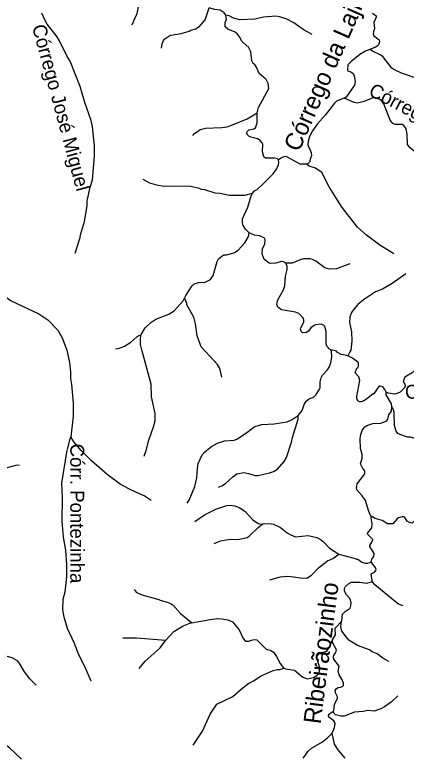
# Model space of a CAD drawing. Extents: x 393 to 446.6, y 8175.5 to 8231.
# Drawn here: x 426.13 to 430.63, y 8175.61 to 8184.16 of the extents above; entities that cross this region are included whole.
import ezdxf
from ezdxf.enums import TextEntityAlignment as Align

# ---------------------------------------------------------------- set-up
doc = ezdxf.new("R2010")
doc.units = 0
doc.header["$LTSCALE"] = 0.064
doc.linetypes.add('LONG_DASHED', pattern=[7.5, 6, -1.5])
doc.layers.add('61', color=7, linetype='Continuous')
doc.layers.add('7', color=7, linetype='Continuous', lineweight=25)
doc.layers.add('9', color=7, linetype='LONG_DASHED', lineweight=25)

msp = doc.modelspace()

# ---------------------------------------------------------------- linework, layer by layer
at = {"layer": '7'}
for points in [[(427.4826, 8184.0466), (427.5145, 8184.1177), (427.5416, 8184.178), (427.5642, 8184.2943), (427.5642, 8184.3976), (427.5093, 8184.5656), (427.506, 8184.6176)], [(427.8211, 8183.7769), (427.829, 8183.8292), (427.8452, 8183.8648), (427.8597, 8183.8857), (427.9033, 8183.9148), (427.9198, 8183.923), (427.926, 8183.9261), (428.0455, 8183.9455), (428.1391, 8183.9745), (428.1585, 8183.9858), (428.215, 8183.9987), (428.2473, 8184.0246), (428.2554, 8184.0246), (428.3216, 8184.1021), (428.3699, 8184.2432)], [(428.5594, 8184.1583), (428.542, 8184.1851), (428.496, 8184.2135), (428.4298, 8184.2232), (428.3699, 8184.2432)], [(426.8263, 8181.4239), (426.886, 8181.6024), (426.8892, 8181.6331), (426.9344, 8181.7849), (426.9635, 8181.9658), (426.9667, 8182.0239), (426.999, 8182.1789), (427.0265, 8182.2661), (427.0507, 8182.5374), (427.0491, 8182.6537), (427.0249, 8182.8733), (427.0103, 8182.9475), (426.9393, 8183.1542), (426.886, 8183.3383), (426.7681, 8183.629), (426.7358, 8183.6823), (426.6438, 8183.868), (426.6099, 8183.9229), (426.5065, 8184.0521), (426.4774, 8184.1037), (426.4451, 8184.1813)], [(428.9217, 8183.0345), (428.9352, 8183.0961), (429.0531, 8183.3157), (429.0482, 8183.3722), (429.0224, 8183.4191), (428.9432, 8183.4853), (428.9142, 8183.5579), (428.8884, 8183.5935), (428.8738, 8183.6031), (428.8651, 8183.6228), (428.8609, 8183.6322), (428.848, 8183.7356), (428.8173, 8183.7985), (428.8076, 8183.8017), (428.7446, 8183.8599), (428.7188, 8183.91), (428.6946, 8183.939), (428.6687, 8183.96), (428.5848, 8183.9972), (428.5525, 8184.0246), (428.5525, 8184.0682), (428.5686, 8184.1102), (428.5594, 8184.1583)], [(429.5529, 8183.9345), (429.4503, 8183.9907), (429.3437, 8184.0682), (429.2533, 8184.1134), (429.1758, 8184.1392), (429.1371, 8184.1473), (428.9917, 8184.1344), (428.8948, 8184.1118), (428.7204, 8184.1021), (428.6494, 8184.1215), (428.5977, 8184.1489), (428.5594, 8184.1583)], [(428.18, 8182.7749), (428.2021, 8182.8006), (428.2441, 8182.8297), (428.2667, 8182.8426), (428.3264, 8182.8587), (428.5137, 8182.8668), (428.5751, 8182.8748), (428.6171, 8182.8878), (428.8044, 8182.9653), (428.9217, 8183.0345)], [(429.1657, 8182.4939), (429.154, 8182.5067), (429.1209, 8182.5131), (429.0176, 8182.5131), (428.9965, 8182.5293), (428.9804, 8182.5858), (428.9869, 8182.6762), (428.9788, 8182.6892), (428.9562, 8182.7182), (428.9239, 8182.7344), (428.8464, 8182.7538), (428.8238, 8182.7667), (428.8124, 8182.7763), (428.7995, 8182.8054), (428.8044, 8182.8184), (428.8254, 8182.8377), (428.8819, 8182.849), (428.9013, 8182.8635), (428.919, 8182.9217), (428.9217, 8183.0345)], [(428.8689, 8182.1099), (428.891, 8182.1367), (428.919, 8182.1547), (428.9917, 8182.2209), (429.1031, 8182.3323), (429.1435, 8182.3856), (429.1677, 8182.4373), (429.1709, 8182.4631), (429.1657, 8182.4939)], [(427.6061, 8182.2736), (427.6837, 8182.2305), (427.7613, 8182.2063), (427.8517, 8182.1934), (427.9712, 8182.1967), (428.1585, 8182.1902), (428.2537, 8182.1692), (428.2748, 8182.1579), (428.3135, 8182.153), (428.433, 8182.1159), (428.4944, 8182.1111), (428.6009, 8182.0884), (428.7786, 8182.09), (428.8689, 8182.1099)], [(428.8273, 8181.6561), (428.7866, 8181.6961), (428.7592, 8181.7397), (428.7511, 8181.772), (428.7511, 8181.8156), (428.8125, 8181.9496), (428.8526, 8182.0797), (428.8689, 8182.1099)], [(428.0861, 8180.905), (428.102, 8180.9366), (428.1681, 8181.0437), (428.1972, 8181.0679), (428.2457, 8181.0856), (428.3216, 8181.0905), (428.3846, 8181.1212), (428.4152, 8181.1648), (428.4588, 8181.3263), (428.4766, 8181.3554), (428.5137, 8181.3892), (428.5364, 8181.4021), (428.567, 8181.4021), (428.6413, 8181.4215), (428.6607, 8181.428), (428.7011, 8181.4554), (428.7801, 8181.541), (428.8205, 8181.6137), (428.8273, 8181.6561)], [(429.2516, 8181.3073), (429.2242, 8181.3214), (429.1952, 8181.3247), (429.1338, 8181.3085), (429.0692, 8181.3037), (429.0595, 8181.3053), (429.0078, 8181.3473), (428.9965, 8181.3618), (428.9772, 8181.4135), (428.9836, 8181.4716), (429.0095, 8181.5298), (429.0127, 8181.5766), (429.003, 8181.5976), (428.9465, 8181.6218), (428.8884, 8181.6299), (428.8273, 8181.6561)], [(429.7687, 8180.3121), (429.7396, 8180.3272), (429.7361, 8180.3396), (429.7216, 8180.3542), (429.7151, 8180.38), (429.7135, 8180.5221), (429.699, 8180.5786), (429.6861, 8180.5899), (429.657, 8180.6061), (429.5924, 8180.5996), (429.5775, 8180.5899), (429.5375, 8180.5641), (429.5149, 8180.5285), (429.489, 8180.5092), (429.4439, 8180.506), (429.4261, 8180.5205), (429.4196, 8180.548), (429.4228, 8180.5657), (429.4584, 8180.6287), (429.4584, 8180.6545), (429.4519, 8180.6707), (429.4422, 8180.6884), (429.4003, 8180.7272), (429.3599, 8180.745), (429.2016, 8180.7724), (429.1596, 8180.8031), (429.1483, 8180.8305), (429.1564, 8180.8774), (429.2242, 8181.0001), (429.2388, 8181.0453), (429.2484, 8181.1584), (429.2646, 8181.2359), (429.2662, 8181.273), (429.2516, 8181.3073)], [(429.9862, 8181.2983), (429.8314, 8181.2439), (429.7539, 8181.2391), (429.699, 8181.252), (429.594, 8181.3295), (429.5569, 8181.3505), (429.5311, 8181.3569), (429.4536, 8181.3553), (429.4148, 8181.3472), (429.3244, 8181.3085), (429.2516, 8181.3073)], [(430.6311, 8181.1829), (430.4741, 8181.0744), (430.3611, 8181.0082), (430.2836, 8180.9758), (430.1447, 8180.887), (430.0768, 8180.8321), (430.0365, 8180.7821), (430.0074, 8180.7385), (429.988, 8180.6868), (429.9815, 8180.6255), (430.0042, 8180.5189), (430.0106, 8180.4091), (429.9977, 8180.3057), (429.9881, 8180.2889), (429.9622, 8180.2431)], [(427.5833, 8180.4796), (427.6336, 8180.5641), (427.6967, 8180.6238), (427.7548, 8180.6626), (427.9066, 8180.7223), (427.9679, 8180.7611), (428.0713, 8180.8757), (428.0861, 8180.905)], [(428.5141, 8179.9975), (428.5008, 8180.0668), (428.4879, 8180.1055), (428.4653, 8180.1443), (428.278, 8180.3445), (428.2295, 8180.4705), (428.2117, 8180.6093), (428.1908, 8180.6868), (428.11, 8180.8289), (428.11, 8180.8435), (428.0869, 8180.9028), (428.0861, 8180.905)], [(427.2894, 8180.3224), (427.336, 8180.3317), (427.3946, 8180.3542), (427.4674, 8180.401), (427.5352, 8180.4591), (427.561, 8180.4753), (427.5833, 8180.4796)], [(427.6224, 8179.0906), (427.645, 8179.156), (427.674, 8179.2723), (427.7289, 8179.4273), (427.7467, 8179.4951), (427.7467, 8179.5791), (427.7063, 8179.7729), (427.7031, 8179.9182), (427.5965, 8180.2961), (427.5804, 8180.3736), (427.5771, 8180.4252), (427.5833, 8180.4796)], [(429.3936, 8179.5546), (429.4374, 8179.613), (429.4616, 8179.6824), (429.4842, 8179.7212), (429.5246, 8179.7518), (429.5666, 8179.7647), (429.6005, 8179.797), (429.6344, 8179.8504), (429.6441, 8179.8762), (429.6473, 8179.944), (429.657, 8179.9892), (429.6731, 8180.0183), (429.7313, 8180.0829), (429.749, 8180.112), (429.7668, 8180.1636), (429.7712, 8180.1855), (429.7797, 8180.2282), (429.7765, 8180.2928), (429.7687, 8180.3121)], [(429.9622, 8180.2431), (429.9134, 8180.2532), (429.8863, 8180.2589), (429.8459, 8180.2799), (429.8314, 8180.2944), (429.7687, 8180.3121)], [(430.4033, 8179.823), (430.3905, 8179.8568), (430.3675, 8179.8859), (430.3352, 8179.8939), (430.3255, 8179.8923), (430.3078, 8179.873), (430.2625, 8179.8068), (430.2544, 8179.8068), (430.1802, 8179.7454), (430.1479, 8179.7244), (430.1156, 8179.7131), (430.101, 8179.7131), (430.0833, 8179.7228), (430.0688, 8179.747), (430.0672, 8179.7761), (430.1011, 8179.9602), (430.0898, 8180.0022), (430.0478, 8180.0474), (430.0671, 8180.1006), (430.0785, 8180.1071), (430.0865, 8180.1216), (430.0849, 8180.1604), (430.0768, 8180.1701), (430.0187, 8180.2169), (429.9622, 8180.2431)], [(430.4696, 8179.6566), (430.4644, 8179.6889), (430.4062, 8179.7922), (430.4033, 8179.823)], [(430.2381, 8178.3946), (430.2288, 8178.3994), (430.206, 8178.452), (430.1673, 8178.5795), (430.1301, 8178.6344), (430.0671, 8178.7038), (430.0639, 8178.7265), (430.0704, 8178.7717), (430.1576, 8178.8847), (430.1576, 8178.9202), (430.135, 8178.9477), (430.1091, 8179.001), (430.1269, 8179.0656), (430.1269, 8179.1092), (430.1075, 8179.1786), (430.1059, 8179.2917), (430.114, 8179.3369), (430.1285, 8179.3853), (430.143, 8179.4079), (430.1608, 8179.4273), (430.1834, 8179.4402), (430.2513, 8179.4628), (430.3449, 8179.4676), (430.4127, 8179.4967), (430.424, 8179.5145), (430.4353, 8179.5629), (430.4649, 8179.6054), (430.4696, 8179.6566)], [(431.2298, 8179.431), (431.12, 8179.4063), (430.9618, 8179.3287), (430.8875, 8179.2997), (430.8229, 8179.29), (430.7518, 8179.29), (430.6808, 8179.3094), (430.655, 8179.3094), (430.6033, 8179.3223), (430.5387, 8179.3514), (430.5177, 8179.3772), (430.5015, 8179.4402), (430.4983, 8179.5888), (430.4934, 8179.6146), (430.4696, 8179.6566)], [(428.1167, 8178.5506), (428.1391, 8178.5843), (428.2053, 8178.7394), (428.2263, 8178.8395), (428.2327, 8178.9493), (428.2425, 8179.0058), (428.2892, 8179.1043), (428.3199, 8179.1399), (428.3942, 8179.2012), (428.4637, 8179.2383), (428.546, 8179.2642), (428.6558, 8179.2722), (428.6881, 8179.2852), (428.785, 8179.3481), (428.8835, 8179.424), (428.9061, 8179.4337), (428.9756, 8179.4515), (429.1177, 8179.4596), (429.2662, 8179.4854), (429.3244, 8179.5096), (429.3936, 8179.5546)], [(428.4742, 8178.734), (428.5153, 8178.7474), (428.5573, 8178.7733), (428.6397, 8178.8508), (428.6881, 8178.8847), (428.7689, 8178.9008), (428.8206, 8178.8912), (428.8981, 8178.8669), (428.9336, 8178.8669), (429.0628, 8178.896), (429.108, 8178.9121), (429.1532, 8178.938), (429.2323, 8179.0268), (429.2581, 8179.0753), (429.3147, 8179.2497), (429.3259, 8179.3046), (429.3905, 8179.5145), (429.3936, 8179.5546)], [(426.1883, 8178.9856), (426.1476, 8178.9833), (426.1465, 8178.983), (425.7977, 8178.8912), (425.6556, 8178.8605), (425.5651, 8178.8314), (425.5587, 8178.8249), (425.4553, 8178.8023), (425.3778, 8178.7991), (425.1711, 8178.8104), (425.0373, 8178.805)], [(428.205, 8178.3401), (428.3167, 8178.4164), (428.4443, 8178.4794), (428.5719, 8178.5214), (428.6106, 8178.5262), (428.6623, 8178.5198), (428.714, 8178.4987), (428.7786, 8178.4568), (428.869, 8178.3583), (428.9304, 8178.3147), (428.9696, 8178.3085), (428.9843, 8178.3111)], [(430.2335, 8177.8736), (430.2415, 8177.9045), (430.2609, 8177.9352), (430.2658, 8177.9708), (430.2157, 8178.0515), (430.2157, 8178.0628), (430.2415, 8178.0999), (430.2528, 8178.1322), (430.1931, 8178.1871), (430.1915, 8178.2033), (430.2383, 8178.2662), (430.2431, 8178.3099), (430.2302, 8178.3793), (430.2372, 8178.3929), (430.2381, 8178.3946)], [(430.883, 8178.3693), (430.8679, 8178.3716), (430.839, 8178.3889), (430.7825, 8178.3906), (430.7518, 8178.3728), (430.7018, 8178.3211), (430.6711, 8178.326), (430.6452, 8178.3437), (430.621, 8178.3857), (430.6146, 8178.3857), (430.613, 8178.3922), (430.5904, 8178.3922), (430.5452, 8178.3809), (430.5257, 8178.3664), (430.4822, 8178.3098), (430.4192, 8178.3098), (430.3578, 8178.3502), (430.2771, 8178.3744), (430.2381, 8178.3946)], [(428.4273, 8178.0845), (428.5008, 8178.1161), (428.5396, 8178.1257), (428.6171, 8178.1354), (428.6978, 8178.1306), (428.8044, 8178.1564), (428.8302, 8178.1709), (428.9336, 8178.2711), (428.9843, 8178.3111)], [(428.9843, 8178.3111), (429.0022, 8178.3143), (429.0854, 8178.3131), (429.1112, 8178.3066), (429.1192, 8178.2985), (429.1338, 8178.2969), (429.1887, 8178.2711), (429.2662, 8178.2081), (429.2985, 8178.1887), (429.3631, 8178.1629), (429.5085, 8178.1774), (429.6053, 8178.1532), (429.657, 8178.1273), (429.6893, 8178.1015), (429.7539, 8178.0321), (429.8591, 8177.9612)], [(429.068, 8177.6663), (429.1887, 8177.7027), (429.2662, 8177.7091), (429.3437, 8177.7043), (429.4148, 8177.6897), (429.4923, 8177.6881), (429.5472, 8177.722), (429.6279, 8177.8076), (429.7313, 8177.8868), (429.7894, 8177.9142), (429.8591, 8177.9612)], [(429.8591, 8177.9612), (430.0478, 8177.9142), (430.0623, 8177.9061), (430.0785, 8177.9061), (430.1237, 8177.8722), (430.1673, 8177.8593), (430.1931, 8177.8593), (430.2335, 8177.8736)], [(430.2399, 8177.6533), (430.243, 8177.6601), (430.2319, 8177.7366), (430.2706, 8177.7576), (430.2868, 8177.7753), (430.2884, 8177.7867), (430.2803, 8177.8076), (430.2335, 8177.8736)], [(429.889, 8177.1878), (429.896, 8177.2018), (429.904, 8177.2732), (429.9315, 8177.3022), (429.9896, 8177.3442), (429.9993, 8177.3733), (430.0009, 8177.4056), (429.988, 8177.4524), (429.9493, 8177.4944), (429.9234, 8177.5396), (429.9266, 8177.5687), (429.938, 8177.5897), (429.9735, 8177.6268), (430.0058, 8177.6397), (430.1027, 8177.6429), (430.1802, 8177.6284), (430.236, 8177.6449), (430.2399, 8177.6533)], [(430.5983, 8177.3706), (430.5459, 8177.3893), (430.5112, 8177.4136), (430.2755, 8177.609), (430.2419, 8177.6508), (430.2399, 8177.6533)], [(427.506, 8177.556), (427.5304, 8177.5281), (427.5949, 8177.4944), (427.7903, 8177.4427), (427.8065, 8177.433), (427.8969, 8177.4071), (427.9308, 8177.391), (427.9518, 8177.3813), (428.039, 8177.2829), (428.165, 8177.1771), (428.1672, 8177.1752)], [(428.1672, 8177.1752), (428.3813, 8177.2134), (428.4621, 8177.2231), (428.4645, 8177.2229), (428.5137, 8177.2198), (428.5831, 8177.2085), (428.6365, 8177.1859), (428.7155, 8177.0923), (428.7592, 8176.9922), (428.785, 8176.9631), (428.8238, 8176.9631), (428.8561, 8176.976), (428.8884, 8176.9808), (428.9174, 8176.9776), (429.0256, 8176.8694), (429.0692, 8176.8613), (429.108, 8176.8355), (429.1419, 8176.7871), (429.1838, 8176.708), (429.224, 8176.6553), (429.2266, 8176.6541)], [(427.8691, 8176.9748), (427.9631, 8177.0729), (428.0713, 8177.1407), (428.1456, 8177.1714), (428.1672, 8177.1752)], [(429.7885, 8176.9797), (429.8217, 8177.0374), (429.8185, 8177.1133), (429.889, 8177.1878)], [(430.435, 8176.7297), (430.3675, 8176.7677), (430.2997, 8176.8162), (430.2448, 8176.8404), (430.2125, 8176.863), (430.0736, 8176.9146), (429.9751, 8176.9744), (429.8943, 8177.0794), (429.8847, 8177.1278), (429.889, 8177.1878)], [(427.3758, 8176.9996), (427.5319, 8177.0002), (427.8691, 8176.9748)], [(427.5639, 8176.6489), (427.6336, 8176.7338), (427.8032, 8176.8856), (427.8691, 8176.9748)], [(429.2266, 8176.6541), (429.2484, 8176.6434), (429.3502, 8176.6288), (429.4471, 8176.5513), (429.4988, 8176.5319), (429.5698, 8176.5448), (429.6053, 8176.5675), (429.6351, 8176.5968), (429.6397, 8176.6585), (429.6095, 8176.7563), (429.6106, 8176.7958), (429.6426, 8176.829), (429.7218, 8176.8499), (429.7533, 8176.8988), (429.7885, 8176.9797)], [(429.7911, 8176.1544), (429.803, 8176.162), (429.8104, 8176.2397), (429.8459, 8176.3043), (429.8443, 8176.322), (429.8201, 8176.3689), (429.8168, 8176.3947), (429.8314, 8176.4189), (429.8508, 8176.4318), (429.8831, 8176.435), (429.9073, 8176.4463), (429.9137, 8176.4528), (429.9137, 8176.4787), (429.8992, 8176.5174), (429.8621, 8176.5756), (429.854, 8176.6143), (429.8637, 8176.6741), (429.8039, 8176.7564), (429.7991, 8176.7823), (429.8023, 8176.8032), (429.8265, 8176.8339), (429.8346, 8176.863), (429.7908, 8176.939), (429.7885, 8176.9797)], [(426.3775, 8176.458), (426.3047, 8176.5304), (426.2449, 8176.6111), (426.182, 8176.716), (426.1626, 8176.737), (426.1012, 8176.7709), (426.0173, 8176.7952), (425.9204, 8176.8), (425.7718, 8176.821), (425.5619, 8176.8178), (425.4941, 8176.8113), (425.3972, 8176.8178), (425.3003, 8176.8387), (425.2783, 8176.8383), (425.2772, 8176.8383)], [(428.1827, 8175.767), (428.2909, 8175.9297), (428.3813, 8176.1234), (428.4572, 8176.2397), (428.6397, 8176.3269), (428.7349, 8176.4109), (428.8254, 8176.4803), (428.8367, 8176.4861), (428.8787, 8176.5077), (428.9675, 8176.5658), (429.1048, 8176.6256), (429.1564, 8176.6385), (429.1823, 8176.6385), (429.2264, 8176.654), (429.2266, 8176.6541)], [(430.5401, 8176.3352), (430.4612, 8176.2639), (430.3837, 8176.2074), (430.3449, 8176.1864), (430.2674, 8176.1605), (430.1947, 8176.167), (430.1382, 8176.1557), (430.0397, 8176.1476), (429.9202, 8176.1024), (429.8831, 8176.1024), (429.8217, 8176.1169), (429.7925, 8176.1527), (429.7911, 8176.1544)], [(429.7825, 8175.9062), (429.8088, 8175.9716), (429.8168, 8176.0136), (429.8088, 8176.0362), (429.8023, 8176.0475), (429.7442, 8176.0911), (429.7426, 8176.1105), (429.7555, 8176.1315), (429.7911, 8176.1544)], [(429.4514, 8175.6186), (429.4649, 8175.6383), (429.4758, 8175.6542), (429.5052, 8175.6971), (429.5472, 8175.7342), (429.6715, 8175.8069), (429.7313, 8175.8521), (429.7825, 8175.9062)], [(429.9317, 8175.6201), (429.8524, 8175.7149), (429.812, 8175.7811), (429.7825, 8175.9062)], [(426.2093, 8175.6077), (426.198, 8175.6183), (426.0705, 8175.7375), (426.0447, 8175.7569), (425.9979, 8175.7795), (425.9204, 8175.8037), (425.6975, 8175.8569), (425.6588, 8175.8747), (425.5651, 8175.8925)]]:
    msp.add_lwpolyline(points, dxfattribs=at)
at = {"layer": '9'}
for points in [[(430.2469, 8184.1789), (430.2888, 8184.1498), (430.2912, 8184.1358), (430.2644, 8184.073), (430.2691, 8184.0049), (430.2596, 8183.9652), (430.254, 8183.9421), (430.2598, 8183.9246), (430.325, 8183.8734), (430.3262, 8183.8496), (430.3146, 8183.817), (430.3006, 8183.7995), (430.2808, 8183.7879), (430.2165, 8183.7637)], [(430.2165, 8183.7637), (430.1673, 8183.7452), (430.1011, 8183.7049), (429.9977, 8183.6225), (429.9654, 8183.5854), (429.959, 8183.5256), (429.9654, 8183.5159), (429.9994, 8183.5046), (430.0252, 8183.4869), (430.0365, 8183.4594), (430.0462, 8183.3965), (430.0413, 8183.3545), (429.9453, 8183.213), (429.9201, 8183.2029)], [(432.0354, 8182.7699), (431.9371, 8182.9055), (431.8386, 8183.0186), (431.7595, 8183.0654), (431.6884, 8183.0912), (431.6755, 8183.0896), (431.5964, 8183.1252), (431.4801, 8183.2075), (431.317, 8183.3415), (431.2702, 8183.3577), (431.1943, 8183.3641), (431.0764, 8183.3609), (431.0264, 8183.3657), (430.7712, 8183.4271), (430.5791, 8183.4917), (430.4935, 8183.5321), (430.4708, 8183.5499), (430.3643, 8183.6806), (430.3352, 8183.7016), (430.2464, 8183.7436), (430.2168, 8183.7635), (430.2165, 8183.7637)], [(429.9201, 8183.2029), (429.8324, 8183.1676), (429.8104, 8183.1445), (429.7038, 8183.0073), (429.615, 8182.9088), (429.5569, 8182.8297), (429.523, 8182.7635), (429.5068, 8182.7086), (429.5052, 8182.6682), (429.5407, 8182.5794), (429.544, 8182.539), (429.5395, 8182.5235), (429.523, 8182.4663), (429.5045, 8182.4474), (429.487, 8182.4439)], [(430.7895, 8182.4213), (430.7557, 8182.4755), (430.7441, 8182.5127), (430.7514, 8182.5569), (430.742, 8182.5778), (430.7262, 8182.5932), (430.6801, 8182.6314), (430.6509, 8182.6698), (430.6475, 8182.7914), (430.6356, 8182.8506), (430.6065, 8182.891), (430.5889, 8182.902), (430.5085, 8182.9008), (430.4829, 8182.9136), (430.4515, 8182.9508), (430.377, 8183.1387), (430.3421, 8183.1853), (430.2723, 8183.2126), (430.2502, 8183.208), (430.1523, 8183.1638), (430.0755, 8183.1469), (430.0347, 8183.1527), (429.9209, 8183.2025), (429.9201, 8183.2029)], [(429.487, 8182.4439), (429.4148, 8182.4463), (429.2614, 8182.5277), (429.2387, 8182.5325), (429.2081, 8182.5212), (429.1657, 8182.4939)], [(430.4917, 8181.416), (430.3336, 8181.5136), (430.177, 8181.6298), (430.0736, 8181.7219), (429.8976, 8181.9464), (429.8621, 8181.9996), (429.749, 8182.1837), (429.6635, 8182.3484), (429.5908, 8182.4001), (429.5181, 8182.4227), (429.487, 8182.4439)], [(425.9187, 8181.013), (425.9268, 8181.0114), (425.9817, 8180.9549), (426.0916, 8180.8757), (426.4113, 8180.7256), (426.513, 8180.6578), (426.6276, 8180.5382), (426.6793, 8180.4478), (426.731, 8180.3089), (426.7633, 8180.1669), (426.773, 8180.0571), (426.773, 8179.9828), (426.7859, 8179.9117), (426.8053, 8179.6986), (426.8053, 8179.55), (426.7757, 8179.3118)], [(430.7809, 8180.1097), (430.7472, 8180.0893), (430.7029, 8180.0463), (430.6583, 8180.0205), (430.621, 8179.9989), (430.6001, 8179.9456), (430.6188, 8179.9171), (430.6227, 8179.8986), (430.6143, 8179.8733), (430.5644, 8179.8239), (430.538, 8179.8116), (430.5032, 8179.8035), (430.4273, 8179.8132), (430.4033, 8179.823)], [(427.0126, 8176.5016), (426.9344, 8176.6789), (426.8699, 8176.8049), (426.8182, 8176.9373), (426.7407, 8177.1085), (426.7003, 8177.2376), (426.6874, 8177.3216), (426.689, 8177.4476), (426.7116, 8177.5299), (426.731, 8177.7027), (426.731, 8177.8416), (426.7213, 8178.0079), (426.6922, 8178.1581), (426.6761, 8178.3422), (426.6809, 8178.6102), (426.6729, 8178.7797), (426.7375, 8179.1641), (426.7671, 8179.2784), (426.7757, 8179.3118)], [(427.7007, 8178.5797), (427.6224, 8178.6328), (427.5269, 8178.6749), (427.4431, 8178.7119), (427.3446, 8178.7684), (427.1944, 8178.8782), (427.0152, 8179.0365), (426.8973, 8179.1544), (426.8133, 8179.2545), (426.7945, 8179.2832), (426.7757, 8179.3118)]]:
    msp.add_lwpolyline(points, dxfattribs=at)

# ---------------------------------------------------------------- texts
at = {"layer": '61'}
for s, height, rotation, p in [('Córrego da Lajinha', 0.2, 66.318, (429.8591, 8183.6171)), ('Córrego José Miguel', 0.16, 285.154, (426.5876, 8183.0747)), ('Córrego Tamboril', 0.16, 332.488, (430.9287, 8182.858)), ('Córrego Lajeadinho', 0.16, 6.955, (431.5639, 8179.8538)), ('Córr. Pontezinha', 0.16, 270, (426.7712, 8178.4308)), ('Ribeirãozinho', 0.2, 82.656, (429.7547, 8176.8152))]:
    msp.add_text(s, height=height, rotation=rotation, dxfattribs=at).set_placement(p, align=Align.CENTER)

doc.saveas('drawing.dxf')
